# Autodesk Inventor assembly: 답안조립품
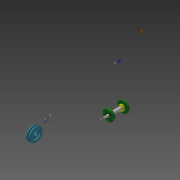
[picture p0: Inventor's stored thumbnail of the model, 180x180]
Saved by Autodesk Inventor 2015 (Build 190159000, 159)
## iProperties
Created: 2018-12
Part Number: 답안조립품
Document SubType Name: Assembly
Designer: CAD02
Author: CAD02
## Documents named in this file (15)
- C:\Users\CAD02\Desktop\481207V1060\답안조립품.iam
- C:\Users\CAD02\Desktop\481207V1060\V벨트풀리.ipt
- C:\Users\CAD02\Desktop\481207V1060\고무캡.ipt
- C:\Users\CAD02\Desktop\481207V1060\너트 M8.ipt
- 너트 M8.ipt
- C:\Users\CAD02\Desktop\481207V1060\뒤커버.ipt
- C:\Users\CAD02\Desktop\481207V1060\베어링 15 x 32 x 9.ipt
- C:\Users\CAD02\Desktop\481207V1060\본체.ipt
- C:\Users\CAD02\Desktop\481207V1060\볼트 M4 x 12.ipt
- C:\Users\CAD02\Desktop\481207V1060\스프링와셔 8.ipt
- C:\Users\CAD02\Desktop\481207V1060\앞커버.ipt
- C:\Users\CAD02\Desktop\481207V1060\오일 실 15 25 7.ipt
- C:\Users\CAD02\Desktop\481207V1060\와셔 8x17.ipt
- C:\Users\CAD02\Desktop\481207V1060\축.ipt
- C:\Users\CAD02\Desktop\481207V1060\키 3 x 3 x 12.ipt
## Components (2 placed, 2 different names)
1. V벨트풀리:1
2. 고무캡:1
